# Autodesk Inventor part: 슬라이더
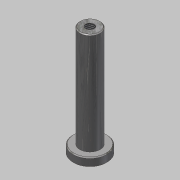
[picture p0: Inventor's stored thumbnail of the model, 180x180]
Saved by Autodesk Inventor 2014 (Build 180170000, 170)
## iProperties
Created: 2016-02
Part Number: 슬라이더
Material: 스테인리스강
Document SubType Name: Modeling
Designer: mduedu
Density: 8.08 g/cm^3
Appearance: 반광택
Author: mduedu
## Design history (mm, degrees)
sketch "스케치1"
  geometry: C1 r 10 at (0, 0); 1 further point
  constraints: 1 centre point, 1 coincident
  dimensions: "d0" = 20 diameter of C1
extrude "돌출1" new body sketch "스케치1" distance "d1" = 5; taper "d2" = 0 deg
sketch "스케치2"
  geometry: C1 r 6 at (0, 0); 1 further point
  constraints: 1 centre point, 1 coincident
  dimensions: "d3" = 12 diameter of C1
extrude "돌출2" join sketch "스케치2" distance "d4" = 60; taper "d5" = 0 deg
chamfer "모따기1" distance "d6" = 0.5; stored, may be unused: second distance "d7" = 2, angle "d8" = 45 deg
hole "구멍1" diameter "d11" = 4.917; stored, may be unused: countersink angle "d15" = 90 deg, drill point angle "d17" = 118 deg; dims "d9" = 10, "d10" = 10, "d12" = 10, "d13" = 4, "d14" = 2, "d16" = 12
chamfer "모따기2" distance "d18" = 0.5; stored, may be unused: second distance "d19" = 2, angle "d20" = 45 deg
node "솔리드1"
